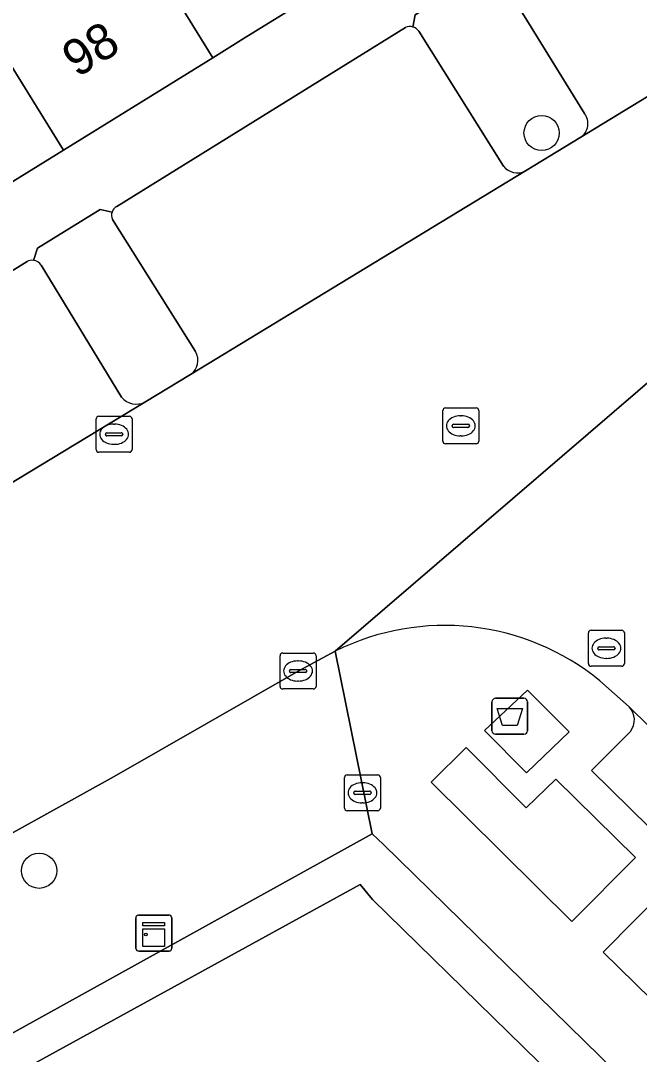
# Model space of a CAD drawing. Extents: x 159888 to 160761, y 384031 to 384750.
# Drawn here: x 160186.63 to 160203.84, y 384505.51 to 384534.23 of the extents above; entities that cross this region are included whole.
import ezdxf

# ---------------------------------------------------------------- set-up
doc = ezdxf.new("R2010")
doc.units = 0
for name, color, linetype in [('IMGEO_Afval_apart_plaats', 7, 'Continuous'), ('IMGEO_Boom', 7, 'Continuous'), ('IMGEO_Brandkraan', 7, 'Continuous'), ('IMGEO_Groenvoorziening', 7, 'Continuous'), ('IMGEO_Kast', 7, 'Continuous'), ('IMGEO_Kolk', 7, 'Continuous'), ('IMGEO_Pand', 7, 'Continuous'), ('IMGEO_Pand_nummerreeks', 7, 'Continuous'), ('IMGEO_Parkeervlak_open', 7, 'Continuous'), ('IMGEO_Rijbaan_lokaal_gesloten', 7, 'Continuous'), ('IMGEO_Rijbaan_lokaal_open', 7, 'Continuous'), ('IMGEO_Rioolput', 7, 'Continuous'), ('IMGEO_Voetpad_open', 7, 'Continuous')]:
    doc.layers.add(name, color=color, linetype=linetype)

msp = doc.modelspace()

# ---------------------------------------------------------------- linework, layer by layer
at = {"layer": 'IMGEO_Afval_apart_plaats'}
for p, q in [((160199.74, 384514.505), (160199.74, 384515.305)), ((160199.74, 384515.305), (160199.74, 384514.505)), ((160199.84, 384515.405), (160200.63, 384515.405)), ((160200.63, 384515.405), (160199.84, 384515.405)), ((160200.73, 384515.305), (160200.73, 384514.505)), ((160200.73, 384514.505), (160200.73, 384515.305)), ((160200.63, 384514.405), (160199.84, 384514.405)), ((160199.84, 384514.405), (160200.63, 384514.405))]:
    msp.add_line(p, q, dxfattribs=at)
msp.add_lwpolyline([(160199.883, 384515.119), (160200.587, 384515.119), (160200.438, 384514.649), (160200.032, 384514.649), (160199.883, 384515.119)], dxfattribs=at)
for centre, start, end in [((160199.84, 384515.305), 90, 180), ((160199.84, 384515.305), 90, 180), ((160200.63, 384515.305), 0, 90), ((160200.63, 384515.305), 360, 90), ((160199.84, 384514.505), 180, 270), ((160199.84, 384514.505), 180, 270), ((160200.63, 384514.505), 270, 0), ((160200.63, 384514.505), 270, 0)]:
    msp.add_arc(centre, 0.1, start, end, dxfattribs=at)
at = {"layer": 'IMGEO_Boom'}
for centre in [(160201.12, 384531.113), (160187.148, 384510.613)]:
    msp.add_circle(centre, 0.489, dxfattribs=at)
at = {"layer": 'IMGEO_Brandkraan'}
for p, q in [((160195.638, 384512.353), (160195.638, 384513.205)), ((160195.713, 384513.279), (160196.565, 384513.279)), ((160196.639, 384513.205), (160196.639, 384512.353)), ((160196.126, 384513.059), (160196.151, 384513.059)), ((160195.897, 384512.773), (160195.897, 384512.785)), ((160196.335, 384512.736), (160195.937, 384512.736)), ((160195.94, 384512.822), (160196.338, 384512.822)), ((160196.381, 384512.785), (160196.381, 384512.773)), ((160196.565, 384512.279), (160195.713, 384512.279)), ((160196.149, 384512.499), (160196.124, 384512.499))]:
    msp.add_line(p, q, dxfattribs=at)
for points in [[(160195.638, 384512.353), (160195.638, 384513.205)], [(160195.713, 384513.279), (160196.565, 384513.279)], [(160196.639, 384513.205), (160196.639, 384512.353)], [(160196.565, 384512.279), (160195.713, 384512.279)]]:
    msp.add_lwpolyline(points, dxfattribs=at)
for centre, radius, start, end in [((160195.715, 384513.203), 0.0765, 91.552, 178.448), ((160195.715, 384513.203), 0.0765, 91.552, 178.448), ((160196.563, 384513.203), 0.0765, 1.552, 88.448), ((160196.563, 384513.203), 0.0765, 1.552, 88.448), ((160195.937, 384512.782), 0.0403, 85.8775, 175.7526), ((160195.934, 384512.772), 0.0366, 178.938, 274.7102), ((160196.338, 384512.779), 0.043, 264.8664, 352.4533), ((160196.342, 384512.784), 0.0386, 1.7309, 96.639), ((160195.715, 384512.355), 0.0765, 181.552, 268.448), ((160195.715, 384512.355), 0.0765, 181.552, 268.448), ((160196.563, 384512.355), 0.0765, 271.552, 358.448), ((160196.563, 384512.355), 0.0765, 271.552, 358.448)]:
    msp.add_arc(centre, radius, start, end, dxfattribs=at)
for centre, major_axis, ratio, start_param, end_param in [((160196.125, 384512.779), (-0.387, 0.002), 0.722429, 4.712389, 7.853982), ((160196.15, 384512.779), (-0.39, 0.002), 0.717154, 1.570796, 4.712389)]:
    msp.add_ellipse(centre, major_axis=major_axis, ratio=ratio, start_param=start_param, end_param=end_param, dxfattribs=at)
at = {"layer": 'IMGEO_Groenvoorziening'}
for points in [[(160199.985, 384535.598), (160199.674, 384535.663), (160197.606, 384534.399), (160197.541, 384534.057)], [(160202.314, 384531.658), (160200.004, 384535.398)], [(160197.706, 384533.943), (160200.062, 384530.194)], [(160200.674, 384530.059), (160202.207, 384530.993)], [(160189.175, 384528.914), (160188.841, 384528.987), (160187.1, 384527.913), (160186.995, 384527.573)], [(160191.496, 384525.038), (160189.191, 384528.711)], [(160187.205, 384527.438), (160189.442, 384523.769)], [(160190.091, 384523.634), (160191.357, 384524.402)]]:
    msp.add_lwpolyline(points, dxfattribs=at)
for points in [[(160201.518, 384513.153), (160200.691, 384512.365), (160199.022, 384514.038), (160198.046, 384513.076), (160201.962, 384509.202), (160203.736, 384510.982)], [(160204.606, 384510.136), (160202.83, 384508.346), (160209.967, 384501.371), (160211.746, 384503.128)]]:
    msp.add_lwpolyline(points, close=True, dxfattribs=at)
for centre, radius, start, end in [((160197.459, 384533.762), 0.306, 36.2058, 74.5124), ((160201.945, 384531.376), 0.464, 304.3518, 37.3669), ((160200.448, 384530.489), 0.486, 217.3824, 297.7385), ((160189.431, 384528.832), 0.268, 162.2191, 206.7941), ((160186.952, 384527.274), 0.302, 32.8208, 81.7087), ((160191.082, 384524.795), 0.48, 304.9446, 30.3987), ((160189.852, 384524.114), 0.536, 220.0591, 296.4396)]:
    msp.add_arc(centre, radius, start, end, dxfattribs=at)
at = {"layer": 'IMGEO_Kast'}
for p, q in [((160189.835, 384508.456), (160189.835, 384509.297)), ((160189.835, 384509.297), (160189.835, 384508.456)), ((160189.91, 384509.381), (160190.751, 384509.381)), ((160190.751, 384509.381), (160189.91, 384509.381)), ((160190.835, 384509.306), (160190.835, 384508.465)), ((160190.835, 384508.465), (160190.835, 384509.306)), ((160190.76, 384508.381), (160189.919, 384508.381)), ((160189.919, 384508.381), (160190.76, 384508.381))]:
    msp.add_line(p, q, dxfattribs=at)
for points in [[(160190.03, 384509.171), (160190.63, 384509.171), (160190.63, 384509.086), (160190.03, 384509.086), (160190.03, 384509.171)], [(160190.03, 384508.996), (160190.63, 384508.996), (160190.63, 384508.507), (160190.03, 384508.507), (160190.03, 384508.996)]]:
    msp.add_lwpolyline(points, dxfattribs=at)
msp.add_circle((160190.114, 384508.845), 0.0377, dxfattribs=at)
for centre, start, end in [((160189.913, 384509.303), 92.4484, 184.2845), ((160189.913, 384509.303), 92.4484, 184.2845), ((160190.757, 384509.303), 2.4484, 94.2845), ((160190.757, 384509.303), 2.4484, 94.2845), ((160189.913, 384508.459), 182.4484, 274.2845), ((160189.913, 384508.459), 182.4484, 274.2845), ((160190.757, 384508.459), 272.4484, 4.2845), ((160190.757, 384508.459), 272.4484, 4.2845)]:
    msp.add_arc(centre, 0.0779, start, end, dxfattribs=at)
at = {"layer": 'IMGEO_Kolk'}
for p, q in [((160188.807, 384523.241), (160189.659, 384523.241)), ((160188.732, 384522.315), (160188.732, 384523.167)), ((160189.22, 384523.021), (160189.245, 384523.021)), ((160189.733, 384523.167), (160189.733, 384522.315)), ((160188.991, 384522.735), (160188.991, 384522.747)), ((160189.429, 384522.698), (160189.031, 384522.698)), ((160189.034, 384522.784), (160189.432, 384522.784)), ((160189.475, 384522.747), (160189.475, 384522.735)), ((160189.243, 384522.461), (160189.218, 384522.461)), ((160189.659, 384522.241), (160188.807, 384522.241)), ((160193.847, 384515.737), (160193.847, 384516.589)), ((160193.922, 384516.663), (160194.774, 384516.663)), ((160194.848, 384516.589), (160194.848, 384515.737)), ((160194.335, 384516.443), (160194.36, 384516.443)), ((160194.106, 384516.157), (160194.106, 384516.169)), ((160194.544, 384516.12), (160194.146, 384516.12)), ((160194.149, 384516.206), (160194.547, 384516.206)), ((160194.59, 384516.169), (160194.59, 384516.157)), ((160194.358, 384515.883), (160194.333, 384515.883)), ((160194.774, 384515.663), (160193.922, 384515.663))]:
    msp.add_line(p, q, dxfattribs=at)
for points in [[(160188.807, 384523.241), (160189.659, 384523.241)], [(160188.732, 384522.315), (160188.732, 384523.167)], [(160189.733, 384523.167), (160189.733, 384522.315)], [(160189.659, 384522.241), (160188.807, 384522.241)], [(160193.847, 384515.737), (160193.847, 384516.589)], [(160193.922, 384516.663), (160194.774, 384516.663)], [(160194.848, 384516.589), (160194.848, 384515.737)], [(160194.774, 384515.663), (160193.922, 384515.663)]]:
    msp.add_lwpolyline(points, dxfattribs=at)
for centre, radius, start, end in [((160188.809, 384523.165), 0.0765, 91.552, 178.448), ((160188.809, 384523.165), 0.0765, 91.552, 178.448), ((160189.657, 384523.165), 0.0765, 1.552, 88.448), ((160189.657, 384523.165), 0.0765, 1.552, 88.448), ((160189.031, 384522.744), 0.0403, 85.8775, 175.7526), ((160189.028, 384522.734), 0.0366, 178.938, 274.7102), ((160189.432, 384522.741), 0.043, 264.8664, 352.4533), ((160189.436, 384522.746), 0.0386, 1.7309, 96.639), ((160188.809, 384522.317), 0.0765, 181.552, 268.448), ((160188.809, 384522.317), 0.0765, 181.552, 268.448), ((160189.657, 384522.317), 0.0765, 271.552, 358.448), ((160189.657, 384522.317), 0.0765, 271.552, 358.448), ((160193.924, 384516.587), 0.0765, 91.552, 178.448), ((160193.924, 384516.587), 0.0765, 91.552, 178.448), ((160194.772, 384516.587), 0.0765, 1.552, 88.448), ((160194.772, 384516.587), 0.0765, 1.552, 88.448), ((160194.146, 384516.166), 0.0403, 85.8775, 175.7526), ((160194.143, 384516.156), 0.0366, 178.938, 274.7102), ((160194.547, 384516.163), 0.043, 264.8664, 352.4533), ((160194.551, 384516.168), 0.0386, 1.7309, 96.639), ((160193.924, 384515.739), 0.0765, 181.552, 268.448), ((160193.924, 384515.739), 0.0765, 181.552, 268.448), ((160194.772, 384515.739), 0.0765, 271.552, 358.448), ((160194.772, 384515.739), 0.0765, 271.552, 358.448)]:
    msp.add_arc(centre, radius, start, end, dxfattribs=at)
for centre, major_axis, ratio, start_param, end_param in [((160189.219, 384522.741), (-0.387, 0.002), 0.722429, 4.712389, 7.853982), ((160189.244, 384522.741), (-0.39, 0.002), 0.717154, 1.570796, 4.712389), ((160194.334, 384516.163), (-0.387, 0.002), 0.722429, 4.712389, 7.853982), ((160194.359, 384516.163), (-0.39, 0.002), 0.717154, 1.570796, 4.712389)]:
    msp.add_ellipse(centre, major_axis=major_axis, ratio=ratio, start_param=start_param, end_param=end_param, dxfattribs=at)
at = {"layer": 'IMGEO_Pand'}
for points in [[(160191.382, 384543.45), (160187.228, 384540.881), (160191.975, 384533.205), (160192.85, 384533.747), (160196.127, 384535.776)], [(160187.228, 384540.881), (160183.074, 384538.312), (160187.822, 384530.635), (160191.975, 384533.205)], [(160183.074, 384538.312), (160178.92, 384535.743), (160183.668, 384528.065), (160187.822, 384530.635)], [(160196.415, 384509.815), (160196.075, 384510.23), (160186.593, 384505.023), (160190.804, 384497.414), (160194.583, 384499.505), (160197.518, 384496.643), (160203.556, 384502.837)]]:
    msp.add_lwpolyline(points, close=True, dxfattribs=at)
at = {"layer": 'IMGEO_Parkeervlak_open'}
for points in [[(160200.004, 384535.398), (160202.314, 384531.658)], [(160202.207, 384530.993), (160207.734, 384534.361)], [(160197.338, 384534.041), (160189.31, 384529.074)], [(160200.062, 384530.194), (160197.706, 384533.943)], [(160191.357, 384524.402), (160200.674, 384530.059)], [(160189.191, 384528.711), (160191.496, 384525.038)], [(160186.813, 384527.543), (160182.726, 384525.013), (160175.651, 384520.656)], [(160189.442, 384523.769), (160187.205, 384527.438)], [(160177.571, 384516.068), (160180.747, 384517.987), (160190.091, 384523.634)], [(160234.606, 384485.229), (160232.947, 384486.549), (160231.049, 384488.176), (160203.557, 384515.169)], [(160203.589, 384514.481), (160202.511, 384513.401), (160229.885, 384486.517), (160231.834, 384484.894), (160233.589, 384483.523)]]:
    msp.add_lwpolyline(points, dxfattribs=at)
for centre, radius, start, end in [((160197.461, 384533.772), 0.296, 74.3871, 114.6261), ((160197.459, 384533.762), 0.306, 36.2058, 74.5124), ((160201.945, 384531.376), 0.464, 304.3518, 37.3669), ((160200.448, 384530.489), 0.486, 217.3824, 297.7385), ((160189.428, 384528.838), 0.264, 116.4834, 163.2046), ((160189.431, 384528.832), 0.268, 162.2191, 206.7941), ((160186.952, 384527.268), 0.308, 81.9284, 116.792), ((160186.952, 384527.274), 0.302, 32.8208, 81.7087), ((160191.082, 384524.795), 0.48, 304.9446, 30.3987), ((160189.852, 384524.114), 0.536, 220.0591, 296.4396), ((160203.169, 384514.806), 0.531, 322.217, 43.109)]:
    msp.add_arc(centre, radius, start, end, dxfattribs=at)
at = {"layer": 'IMGEO_Rijbaan_lokaal_gesloten'}
msp.add_lwpolyline([(160201.888, 384514.471), (160200.73, 384515.635), (160199.533, 384514.507), (160200.701, 384513.335)], close=True, dxfattribs=at)
at = {"layer": 'IMGEO_Rijbaan_lokaal_open'}
for points in [[(160184.709, 384510.733), (160189.233, 384513.236), (160194.348, 384516.163), (160195.384, 384516.714), (160206.625, 384526.362), (160206.965, 384526.653), (160207.672, 384527.208), (160208.363, 384527.623), (160212.649, 384530.34), (160222.306, 384536.124)], [(160207.734, 384534.361), (160202.207, 384530.993), (160200.674, 384530.059), (160191.357, 384524.402), (160190.091, 384523.634), (160180.747, 384517.987)], [(160206.625, 384526.362), (160195.384, 384516.714)], [(160202.743, 384515.892), (160203.557, 384515.169), (160231.049, 384488.176), (160232.947, 384486.549), (160234.606, 384485.229)]]:
    msp.add_lwpolyline(points, dxfattribs=at)
msp.add_arc((160198.426, 384510.596), 6.833, 50.8173, 116.4356, dxfattribs=at)
at = {"layer": 'IMGEO_Rioolput'}
for p, q in [((160198.448, 384523.474), (160199.3, 384523.474)), ((160198.373, 384522.548), (160198.373, 384523.4)), ((160198.861, 384523.254), (160198.886, 384523.254)), ((160199.374, 384523.4), (160199.374, 384522.548)), ((160198.632, 384522.968), (160198.632, 384522.98)), ((160199.07, 384522.931), (160198.672, 384522.931)), ((160198.675, 384523.017), (160199.073, 384523.017)), ((160199.116, 384522.98), (160199.116, 384522.968)), ((160198.884, 384522.694), (160198.859, 384522.694)), ((160199.3, 384522.474), (160198.448, 384522.474)), ((160202.422, 384516.368), (160202.422, 384517.22)), ((160202.497, 384517.294), (160203.349, 384517.294)), ((160203.423, 384517.22), (160203.423, 384516.368)), ((160202.91, 384517.074), (160202.935, 384517.074)), ((160202.681, 384516.788), (160202.681, 384516.8)), ((160203.119, 384516.751), (160202.721, 384516.751)), ((160202.724, 384516.837), (160203.122, 384516.837)), ((160203.165, 384516.8), (160203.165, 384516.788)), ((160202.933, 384516.514), (160202.908, 384516.514)), ((160203.349, 384516.294), (160202.497, 384516.294))]:
    msp.add_line(p, q, dxfattribs=at)
for points in [[(160198.448, 384523.474), (160199.3, 384523.474)], [(160198.373, 384522.548), (160198.373, 384523.4)], [(160199.374, 384523.4), (160199.374, 384522.548)], [(160199.3, 384522.474), (160198.448, 384522.474)], [(160202.422, 384516.368), (160202.422, 384517.22)], [(160202.497, 384517.294), (160203.349, 384517.294)], [(160203.423, 384517.22), (160203.423, 384516.368)], [(160203.349, 384516.294), (160202.497, 384516.294)]]:
    msp.add_lwpolyline(points, dxfattribs=at)
for centre, radius, start, end in [((160198.45, 384523.398), 0.0765, 91.552, 178.448), ((160198.45, 384523.398), 0.0765, 91.552, 178.448), ((160199.298, 384523.398), 0.0765, 1.552, 88.448), ((160199.298, 384523.398), 0.0765, 1.552, 88.448), ((160198.672, 384522.977), 0.0403, 85.8775, 175.7526), ((160198.669, 384522.967), 0.0366, 178.938, 274.7102), ((160199.073, 384522.974), 0.043, 264.8664, 352.4533), ((160199.077, 384522.979), 0.0386, 1.7309, 96.639), ((160198.45, 384522.55), 0.0765, 181.552, 268.448), ((160198.45, 384522.55), 0.0765, 181.552, 268.448), ((160199.298, 384522.55), 0.0765, 271.552, 358.448), ((160199.298, 384522.55), 0.0765, 271.552, 358.448), ((160202.499, 384517.218), 0.0765, 91.552, 178.448), ((160202.499, 384517.218), 0.0765, 91.552, 178.448), ((160203.347, 384517.218), 0.0765, 1.552, 88.448), ((160203.347, 384517.218), 0.0765, 1.552, 88.448), ((160202.721, 384516.797), 0.0403, 85.8775, 175.7526), ((160202.718, 384516.787), 0.0366, 178.938, 274.7102), ((160203.122, 384516.794), 0.043, 264.8664, 352.4533), ((160203.126, 384516.799), 0.0386, 1.7309, 96.639), ((160202.499, 384516.37), 0.0765, 181.552, 268.448), ((160202.499, 384516.37), 0.0765, 181.552, 268.448), ((160203.347, 384516.37), 0.0765, 271.552, 358.448), ((160203.347, 384516.37), 0.0765, 271.552, 358.448)]:
    msp.add_arc(centre, radius, start, end, dxfattribs=at)
for centre, major_axis, ratio, start_param, end_param in [((160198.86, 384522.974), (-0.387, 0.002), 0.722429, 4.712389, 7.853982), ((160198.885, 384522.974), (-0.39, 0.002), 0.717154, 1.570796, 4.712389), ((160202.909, 384516.794), (-0.387, 0.002), 0.722429, 4.712389, 7.853982), ((160202.934, 384516.794), (-0.39, 0.002), 0.717154, 1.570796, 4.712389)]:
    msp.add_ellipse(centre, major_axis=major_axis, ratio=ratio, start_param=start_param, end_param=end_param, dxfattribs=at)
at = {"layer": 'IMGEO_Voetpad_open'}
for points in [[(160226.109, 384551.8), (160225.193, 384553.771), (160221.044, 384551.202), (160216.891, 384548.631), (160212.738, 384546.06), (160208.586, 384543.489), (160204.433, 384540.918), (160200.28, 384538.347), (160196.127, 384535.776), (160192.85, 384533.747), (160191.975, 384533.205), (160187.822, 384530.635), (160183.668, 384528.065)], [(160197.541, 384534.057), (160197.606, 384534.399), (160199.674, 384535.663), (160199.985, 384535.598)], [(160189.31, 384529.074), (160197.338, 384534.041)], [(160186.995, 384527.573), (160187.1, 384527.913), (160188.841, 384528.987), (160189.175, 384528.914)], [(160182.726, 384525.013), (160186.813, 384527.543)], [(160175.365, 384500), (160196.41, 384511.643), (160195.384, 384516.714), (160194.348, 384516.163), (160189.233, 384513.236), (160184.709, 384510.733), (160173.174, 384504.351), (160165.309, 384500), (160136.525, 384484.446), (160132.921, 384482.467), (160129.945, 384480.77)], [(160195.384, 384516.714), (160196.41, 384511.643), (160196.722, 384511.338), (160208.326, 384500), (160242.988, 384466.237), (160244.045, 384468.12), (160234.942, 384477.032), (160237.752, 384479.861), (160242.643, 384477.209), (160243.35, 384478.526), (160246.899, 384475.68)], [(160203.557, 384515.169), (160202.743, 384515.892)], [(160233.589, 384483.523), (160231.834, 384484.894), (160229.885, 384486.517), (160202.511, 384513.401), (160203.589, 384514.481)], [(160208.326, 384500), (160196.722, 384511.338), (160196.41, 384511.643), (160175.365, 384500)], [(160186.593, 384505.023), (160196.075, 384510.23), (160196.415, 384509.815), (160203.556, 384502.837)]]:
    msp.add_lwpolyline(points, dxfattribs=at)
for points in [[(160201.888, 384514.471), (160200.701, 384513.335), (160199.533, 384514.507), (160200.73, 384515.635)], [(160201.518, 384513.153), (160203.736, 384510.982), (160201.962, 384509.202), (160198.046, 384513.076), (160199.022, 384514.038), (160200.691, 384512.365)], [(160204.606, 384510.136), (160211.746, 384503.128), (160209.967, 384501.371), (160202.83, 384508.346)]]:
    msp.add_lwpolyline(points, close=True, dxfattribs=at)
for centre, radius, start, end in [((160197.461, 384533.772), 0.296, 74.3871, 114.6261), ((160189.428, 384528.838), 0.264, 116.4834, 163.2046), ((160186.952, 384527.268), 0.308, 81.9284, 116.792), ((160198.426, 384510.596), 6.833, 50.8173, 116.4356), ((160203.169, 384514.806), 0.531, 322.217, 43.109)]:
    msp.add_arc(centre, radius, start, end, dxfattribs=at)

# ---------------------------------------------------------------- texts
at = {"layer": 'IMGEO_Pand_nummerreeks'}
msp.add_text('98', height=1, rotation=31.7533, dxfattribs=at).set_placement((160188.201, 384532.633))

doc.saveas('drawing.dxf')
